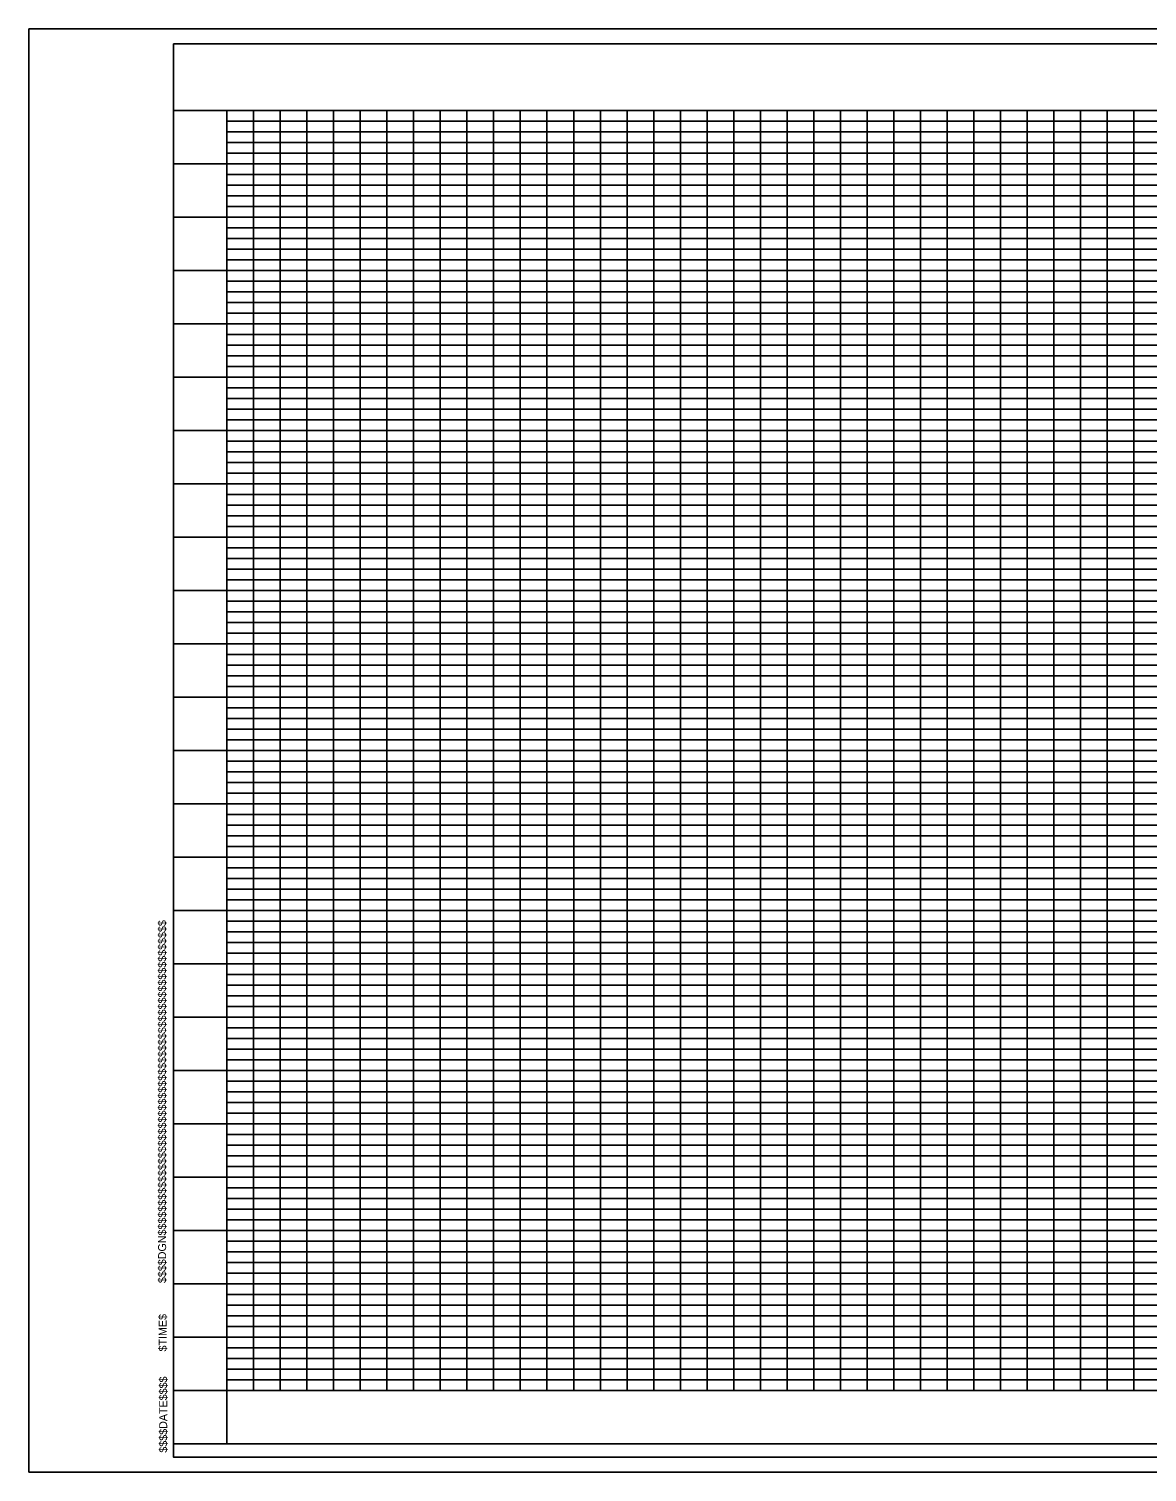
# Model space of a CAD drawing. Extents: x -27 to 606, y -3 to 268.
# Drawn here: x -27.1 to 182.5, y -2.8 to 267.8 of the extents above; entities that cross this region are included whole.
import ezdxf

# ---------------------------------------------------------------- set-up
doc = ezdxf.new("R2010")
doc.units = 0
for name, color, linetype in [('D_CFL_Clip_Boundary_1', 7, 'Continuous'), ('D_CFL_Clip_Boundary_2', 7, 'Continuous'), ('D_CFL_Sheet_Border_ PlotShape', 7, 'Continuous'), ('D_CFL_Sheet_Border_Base', 7, 'Continuous'), ('D_CFL_Sheet_Border_Plan_Plan', 7, 'Continuous'), ('D_CFL_Sheet_Border_PnP', 7, 'Continuous'), ('D_CFL_Sheet_Border_Profile', 7, 'Continuous')]:
    doc.layers.add(name, color=color, linetype=linetype)

msp = doc.modelspace()

# ---------------------------------------------------------------- linework, layer by layer
at = {"layer": 'D_CFL_Clip_Boundary_1'}
msp.add_lwpolyline([(0, 265), (326.25, 265), (326.25, 255), (390, 255), (390, 132.5), (0, 132.5)], close=True, dxfattribs=at)
at = {"layer": 'D_CFL_Clip_Boundary_2'}
msp.add_lwpolyline([(380, 132.5), (10, 132.5), (10, 12.5), (380, 12.5)], close=True, dxfattribs=at)
at = {"layer": 'D_CFL_Sheet_Border_ PlotShape'}
msp.add_line((-27.13, -2.8), (-27.13, -2.8), dxfattribs=at)
msp.add_lwpolyline([(-27.13, -2.8), (395.49, -2.8), (395.49, 267.8), (-27.13, 267.8)], close=True, dxfattribs=at)
at = {"layer": 'D_CFL_Sheet_Border_Base'}
msp.add_lwpolyline([(0, 265), (390, 265), (390, 0), (0, 0)], close=True, dxfattribs=at)
at = {"layer": 'D_CFL_Sheet_Border_Plan_Plan'}
msp.add_line((0, 132.5), (390, 132.5), dxfattribs=at)
at = {"layer": 'D_CFL_Sheet_Border_PnP'}
for p, q in [((0, 132.5), (390, 132.5)), ((10, 2.5), (10, 132.5)), ((10, 130.5), (380, 130.5)), ((15, 12.5), (15, 132.5)), ((20, 12.5), (20, 132.5)), ((25, 12.5), (25, 132.5)), ((30, 12.5), (30, 132.5)), ((35, 12.5), (35, 132.5)), ((40, 12.5), (40, 132.5)), ((45, 12.5), (45, 132.5)), ((50, 12.5), (50, 132.5)), ((55, 12.5), (55, 132.5)), ((60, 12.5), (60, 132.5)), ((65, 12.5), (65, 132.5)), ((70, 12.5), (70, 132.5)), ((75, 12.5), (75, 132.5)), ((80, 12.5), (80, 132.5)), ((85, 12.5), (85, 132.5)), ((90, 12.5), (90, 132.5)), ((95, 12.5), (95, 132.5)), ((100, 12.5), (100, 132.5)), ((105, 12.5), (105, 132.5)), ((110, 12.5), (110, 132.5)), ((115, 12.5), (115, 132.5)), ((120, 12.5), (120, 132.5)), ((125, 12.5), (125, 132.5)), ((130, 12.5), (130, 132.5)), ((135, 12.5), (135, 132.5)), ((140, 12.5), (140, 132.5)), ((145, 12.5), (145, 132.5)), ((150, 12.5), (150, 132.5)), ((155, 12.5), (155, 132.5)), ((160, 12.5), (160, 132.5)), ((165, 12.5), (165, 132.5)), ((170, 12.5), (170, 132.5)), ((175, 12.5), (175, 132.5)), ((180, 12.5), (180, 132.5)), ((10, 128.5), (380, 128.5)), ((10, 126.5), (380, 126.5)), ((10, 124.5), (380, 124.5)), ((10, 122.5), (0, 122.5)), ((10, 122.5), (380, 122.5)), ((10, 120.5), (380, 120.5)), ((10, 118.5), (380, 118.5)), ((10, 116.5), (380, 116.5)), ((10, 114.5), (380, 114.5)), ((10, 112.5), (0, 112.5)), ((10, 112.5), (380, 112.5)), ((10, 110.5), (380, 110.5)), ((10, 108.5), (380, 108.5)), ((10, 106.5), (380, 106.5)), ((10, 104.5), (380, 104.5)), ((10, 102.5), (0, 102.5)), ((10, 102.5), (380, 102.5)), ((10, 100.5), (380, 100.5)), ((10, 98.5), (380, 98.5)), ((10, 96.5), (380, 96.5)), ((10, 92.5), (0, 92.5)), ((10, 94.5), (380, 94.5)), ((10, 92.5), (380, 92.5)), ((10, 90.5), (380, 90.5)), ((10, 88.5), (380, 88.5)), ((10, 86.5), (380, 86.5)), ((10, 84.5), (380, 84.5)), ((10, 82.5), (0, 82.5)), ((10, 82.5), (380, 82.5)), ((10, 80.5), (380, 80.5)), ((10, 78.5), (380, 78.5)), ((10, 76.5), (380, 76.5)), ((10, 74.5), (380, 74.5)), ((10, 72.5), (0, 72.5)), ((10, 72.5), (380, 72.5)), ((10, 70.5), (380, 70.5)), ((10, 68.5), (380, 68.5)), ((10, 66.5), (380, 66.5)), ((10, 62.5), (0, 62.5)), ((10, 64.5), (380, 64.5)), ((10, 62.5), (380, 62.5)), ((10, 60.5), (380, 60.5)), ((10, 58.5), (380, 58.5)), ((10, 56.5), (380, 56.5)), ((10, 54.5), (380, 54.5)), ((10, 52.5), (0, 52.5)), ((10, 52.5), (380, 52.5)), ((10, 50.5), (380, 50.5)), ((10, 48.5), (380, 48.5)), ((10, 46.5), (380, 46.5)), ((10, 44.5), (380, 44.5)), ((10, 42.5), (0, 42.5)), ((10, 42.5), (380, 42.5)), ((10, 40.5), (380, 40.5)), ((10, 38.5), (380, 38.5)), ((10, 36.5), (380, 36.5)), ((10, 32.5), (0, 32.5)), ((10, 34.5), (380, 34.5)), ((10, 32.5), (380, 32.5)), ((10, 30.5), (380, 30.5)), ((10, 28.5), (380, 28.5)), ((10, 26.5), (380, 26.5)), ((10, 24.5), (380, 24.5)), ((10, 22.5), (0, 22.5)), ((10, 22.5), (380, 22.5)), ((10, 20.5), (380, 20.5)), ((10, 18.5), (380, 18.5)), ((10, 16.5), (380, 16.5)), ((10, 14.5), (380, 14.5)), ((10, 12.5), (0, 12.5)), ((10, 12.5), (380, 12.5)), ((0, 2.5), (390, 2.5))]:
    msp.add_line(p, q, dxfattribs=at)
at = {"layer": 'D_CFL_Sheet_Border_Profile'}
for p, q in [((0, 252.5), (390, 252.5)), ((10, 2.5), (10, 252.5)), ((15, 12.5), (15, 252.5)), ((20, 12.5), (20, 252.5)), ((25, 12.5), (25, 252.5)), ((30, 12.5), (30, 252.5)), ((35, 12.5), (35, 252.5)), ((40, 12.5), (40, 252.5)), ((45, 12.5), (45, 252.5)), ((50, 12.5), (50, 252.5)), ((55, 12.5), (55, 252.5)), ((60, 12.5), (60, 252.5)), ((65, 12.5), (65, 252.5)), ((70, 12.5), (70, 252.5)), ((75, 12.5), (75, 252.5)), ((80, 12.5), (80, 252.5)), ((85, 12.5), (85, 252.5)), ((90, 12.5), (90, 252.5)), ((95, 12.5), (95, 252.5)), ((100, 12.5), (100, 252.5)), ((105, 12.5), (105, 252.5)), ((110, 12.5), (110, 252.5)), ((115, 12.5), (115, 252.5)), ((120, 12.5), (120, 252.5)), ((125, 12.5), (125, 252.5)), ((130, 12.5), (130, 252.5)), ((135, 12.5), (135, 252.5)), ((140, 12.5), (140, 252.5)), ((145, 12.5), (145, 252.5)), ((150, 12.5), (150, 252.5)), ((155, 12.5), (155, 252.5)), ((160, 12.5), (160, 252.5)), ((165, 12.5), (165, 252.5)), ((170, 12.5), (170, 252.5)), ((175, 12.5), (175, 252.5)), ((180, 12.5), (180, 252.5)), ((10, 250.5), (380, 250.5)), ((10, 248.5), (380, 248.5)), ((10, 246.5), (380, 246.5)), ((10, 244.5), (380, 244.5)), ((10, 242.5), (0, 242.5)), ((10, 242.5), (380, 242.5)), ((10, 240.5), (380, 240.5)), ((10, 238.5), (380, 238.5)), ((10, 236.5), (380, 236.5)), ((10, 234.5), (380, 234.5)), ((10, 232.5), (0, 232.5)), ((10, 232.5), (380, 232.5)), ((10, 230.5), (380, 230.5)), ((10, 228.5), (380, 228.5)), ((10, 226.5), (380, 226.5)), ((10, 222.5), (0, 222.5)), ((10, 224.5), (380, 224.5)), ((10, 222.5), (380, 222.5)), ((10, 220.5), (380, 220.5)), ((10, 218.5), (380, 218.5)), ((10, 216.5), (380, 216.5)), ((10, 214.5), (380, 214.5)), ((10, 212.5), (0, 212.5)), ((10, 212.5), (380, 212.5)), ((10, 210.5), (380, 210.5)), ((10, 208.5), (380, 208.5)), ((10, 206.5), (380, 206.5)), ((10, 204.5), (380, 204.5)), ((10, 202.5), (0, 202.5)), ((10, 202.5), (380, 202.5)), ((10, 200.5), (380, 200.5)), ((10, 198.5), (380, 198.5)), ((10, 196.5), (380, 196.5)), ((10, 192.5), (0, 192.5)), ((10, 194.5), (380, 194.5)), ((10, 192.5), (380, 192.5)), ((10, 190.5), (380, 190.5)), ((10, 188.5), (380, 188.5)), ((10, 186.5), (380, 186.5)), ((10, 184.5), (380, 184.5)), ((10, 182.5), (0, 182.5)), ((10, 182.5), (380, 182.5)), ((10, 180.5), (380, 180.5)), ((10, 178.5), (380, 178.5)), ((10, 176.5), (380, 176.5)), ((10, 174.5), (380, 174.5)), ((10, 172.5), (0, 172.5)), ((10, 172.5), (380, 172.5)), ((10, 170.5), (380, 170.5)), ((10, 168.5), (380, 168.5)), ((10, 166.5), (380, 166.5)), ((10, 162.5), (0, 162.5)), ((10, 164.5), (380, 164.5)), ((10, 162.5), (380, 162.5)), ((10, 160.5), (380, 160.5)), ((10, 158.5), (380, 158.5)), ((10, 156.5), (380, 156.5)), ((10, 154.5), (380, 154.5)), ((10, 152.5), (0, 152.5)), ((10, 152.5), (380, 152.5)), ((10, 150.5), (380, 150.5)), ((10, 148.5), (380, 148.5)), ((10, 146.5), (380, 146.5)), ((10, 144.5), (380, 144.5)), ((10, 142.5), (0, 142.5)), ((10, 142.5), (380, 142.5)), ((10, 140.5), (380, 140.5)), ((10, 138.5), (380, 138.5)), ((10, 136.5), (380, 136.5)), ((10, 134.5), (380, 134.5)), ((10, 132.5), (0, 132.5)), ((10, 132.5), (380, 132.5)), ((10, 130.5), (380, 130.5)), ((10, 128.5), (380, 128.5)), ((10, 126.5), (380, 126.5)), ((10, 124.5), (380, 124.5)), ((10, 122.5), (0, 122.5)), ((10, 122.5), (380, 122.5)), ((10, 120.5), (380, 120.5)), ((10, 118.5), (380, 118.5)), ((10, 116.5), (380, 116.5)), ((10, 114.5), (380, 114.5)), ((10, 112.5), (0, 112.5)), ((10, 112.5), (380, 112.5)), ((10, 110.5), (380, 110.5)), ((10, 108.5), (380, 108.5)), ((10, 106.5), (380, 106.5)), ((10, 104.5), (380, 104.5)), ((10, 102.5), (0, 102.5)), ((10, 102.5), (380, 102.5)), ((10, 100.5), (380, 100.5)), ((10, 98.5), (380, 98.5)), ((10, 96.5), (380, 96.5)), ((10, 92.5), (0, 92.5)), ((10, 94.5), (380, 94.5)), ((10, 92.5), (380, 92.5)), ((10, 90.5), (380, 90.5)), ((10, 88.5), (380, 88.5)), ((10, 86.5), (380, 86.5)), ((10, 84.5), (380, 84.5)), ((10, 82.5), (0, 82.5)), ((10, 82.5), (380, 82.5)), ((10, 80.5), (380, 80.5)), ((10, 78.5), (380, 78.5)), ((10, 76.5), (380, 76.5)), ((10, 74.5), (380, 74.5)), ((10, 72.5), (0, 72.5)), ((10, 72.5), (380, 72.5)), ((10, 70.5), (380, 70.5)), ((10, 68.5), (380, 68.5)), ((10, 66.5), (380, 66.5)), ((10, 62.5), (0, 62.5)), ((10, 64.5), (380, 64.5)), ((10, 62.5), (380, 62.5)), ((10, 60.5), (380, 60.5)), ((10, 58.5), (380, 58.5)), ((10, 56.5), (380, 56.5)), ((10, 54.5), (380, 54.5)), ((10, 52.5), (0, 52.5)), ((10, 52.5), (380, 52.5)), ((10, 50.5), (380, 50.5)), ((10, 48.5), (380, 48.5)), ((10, 46.5), (380, 46.5)), ((10, 44.5), (380, 44.5)), ((10, 42.5), (0, 42.5)), ((10, 42.5), (380, 42.5)), ((10, 40.5), (380, 40.5)), ((10, 38.5), (380, 38.5)), ((10, 36.5), (380, 36.5)), ((10, 32.5), (0, 32.5)), ((10, 34.5), (380, 34.5)), ((10, 32.5), (380, 32.5)), ((10, 30.5), (380, 30.5)), ((10, 28.5), (380, 28.5)), ((10, 26.5), (380, 26.5)), ((10, 24.5), (380, 24.5)), ((10, 22.5), (0, 22.5)), ((10, 22.5), (380, 22.5)), ((10, 20.5), (380, 20.5)), ((10, 18.5), (380, 18.5)), ((10, 16.5), (380, 16.5)), ((10, 14.5), (380, 14.5)), ((10, 12.5), (0, 12.5)), ((10, 12.5), (380, 12.5)), ((0, 2.5), (390, 2.5))]:
    msp.add_line(p, q, dxfattribs=at)

# ---------------------------------------------------------------- texts
at = {"layer": 'D_CFL_Sheet_Border_Base'}
for s, p in [('$$$$DGN$$$$$$$$$$$$$$$$$$$$$$$$$$$$$$$$$$$$$$$$$$$$$$$$$$$$$', (-1.4, 32.65)), ('$TIME$', (-1.3, 19.83)), ('$$$$DATE$$$$', (-1.2, 0.85))]:
    msp.add_text(s, height=1.5, rotation=90, dxfattribs=at).set_placement(p)

doc.saveas('drawing.dxf')
